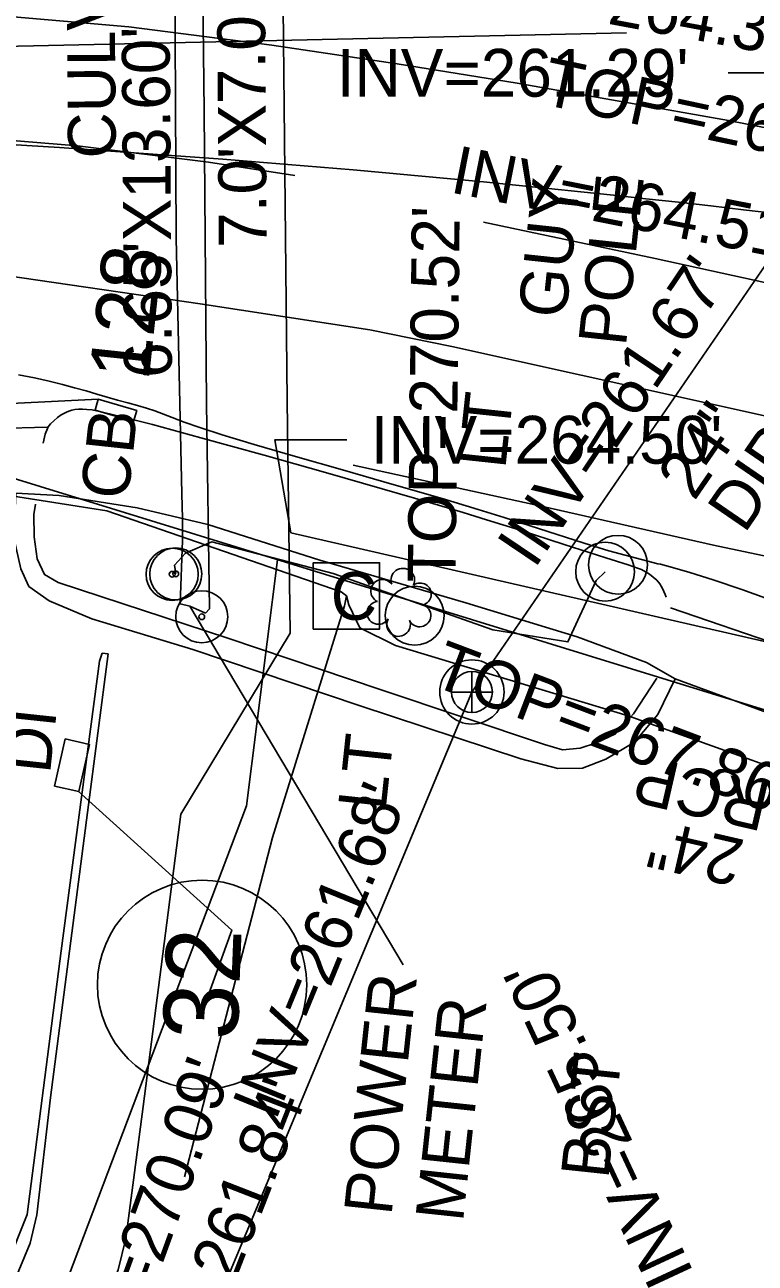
# Model space of a CAD drawing. Extents: x 2100323 to 2109811, y 740376 to 749755.
# Drawn here: x 2105500.5 to 2105561.5, y 742054.8 to 742158.5 of the extents above; entities that cross this region are included whole.
import ezdxf

# ---------------------------------------------------------------- set-up
doc = ezdxf.new("R2010")
doc.units = 0
for name, color, linetype in [('COGO Default Point Number', 7, 'Continuous'), ('Exist Horizontal Alignment', 7, 'Continuous'), ('Exist Other Culture Located Object CELL', 7, 'Continuous'), ('Exist Other Culture Sign CELL', 7, 'Continuous'), ('Exist Property Owner Number CELL', 7, 'Continuous'), ('Exist Right of Way Easement Line', 7, 'Continuous'), ('Exist Right of Way Line', 7, 'Continuous'), ('Exist Roads Curbs', 7, 'Continuous'), ('Exist Roads EOP', 7, 'Continuous'), ('Exist Roads EOP Other', 7, 'Continuous'), ('Exist Roads EOP Text', 7, 'Continuous'), ('Exist Roads EOT', 7, 'Continuous'), ('Exist Structure Major Box Culvert or Tunnel Topo', 7, 'Continuous'), ('Exist Structure Major Box Culvert or Tunnel Topo Text', 7, 'Continuous'), ('Exist Structure Minor Catch Basin', 7, 'Continuous'), ('Exist Structure Minor Catch Basin Text', 7, 'Continuous'), ('Exist Structure Minor Catch Basin Top Elevation', 7, 'Continuous'), ('Exist Structure Minor Drop Inlet', 7, 'Continuous'), ('Exist Structure Minor Drop Inlet Text', 7, 'Continuous'), ('Exist Structure Minor Drop Inlet Top Elevation', 7, 'Continuous'), ('Exist Structure Minor Pipes RCP 18 Inch Invert', 7, 'Continuous'), ('Exist Structure Minor Pipes RCP 24 Inch', 7, 'Continuous'), ('Exist Structure Minor Pipes RCP 24 Inch Invert', 7, 'Continuous'), ('Exist Structure Minor Pipes RCP 24 Inch Leader', 7, 'Continuous'), ('Exist Structure Minor Pipes RCP 24 Inch Text', 7, 'Continuous'), ('Exist Structure Minor Pipes RCP 60 Inch Invert', 7, 'Continuous'), ('Exist Structure Minor Storm Sewer Manhole Text', 7, 'Continuous'), ('Exist Utilities Other Located Object CELL', 7, 'Continuous'), ('Exist Utilities Other Located Object Text', 7, 'Continuous'), ('Exist Utilities Other Pole CELL', 7, 'Continuous'), ('Exist Utilities Other Pole Text', 7, 'Continuous'), ('Exist Utilities Power UG Cable SUE LOS B', 7, 'Continuous'), ('Exist Utilities Sanitary Sewer Manhole CELL', 7, 'Continuous'), ('Exist Utilities Sanitary Sewer Manhole Text', 7, 'Continuous'), ('Exist Utilities Sanitary Sewer UG Line', 7, 'Continuous'), ('Exist Utilities Sanitary Sewer UG Line Invert Elevation', 7, 'Continuous'), ('Exist Utilities Sanitary Sewer UG Line Text', 7, 'Continuous'), ('Exist Utilities TV Pedestal CELL', 7, 'Continuous'), ('Exist Utilities TV UG Cable SUE LOS B', 7, 'Continuous'), ('Exist Utilities Water UG Line SUE LOS B', 7, 'Continuous'), ('Exist Vegetation Shrub CELL', 7, 'Continuous')]:
    doc.layers.add(name, color=color, linetype=linetype)

msp = doc.modelspace()

# ---------------------------------------------------------------- linework, layer by layer
at = {"layer": 'Exist Horizontal Alignment'}
msp.add_arc((2105432.5, 741050.49), 1100, 71.91861, 90.1558, dxfattribs=at)
at = {"layer": 'Exist Other Culture Located Object CELL'}
for radius in [2.18, 0.24]:
    msp.add_circle((2105512.8, 742112.5), radius, dxfattribs=at)
at = {"layer": 'Exist Other Culture Sign CELL'}
for radius in [2.18, 0.24]:
    msp.add_circle((2105515.27, 742108.95), radius, dxfattribs=at)
at = {"layer": 'Exist Property Owner Number CELL'}
msp.add_circle((2105515.3, 742078.15), 8.75, dxfattribs=at)
at = {"layer": 'Exist Right of Way Easement Line'}
msp.add_lwpolyline([(2105410.16, 741805.17), (2105519.01, 742093.13), (2105521.61, 742113.72)], dxfattribs=at)
at = {"layer": 'Exist Right of Way Line'}
msp.add_line((2105563.87, 742100.68), (2105498.4, 742120.88), dxfattribs=at)
at = {"layer": 'Exist Roads Curbs'}
for points in [[(2105502.01, 742123.48), (2105502.19, 742124.22), (2105502.36, 742124.7), (2105502.43, 742124.85), (2105502.63, 742125.08), (2105502.89, 742125.35), (2105503.22, 742125.63), (2105503.52, 742125.84), (2105503.79, 742125.99), (2105504.02, 742126.1), (2105504.23, 742126.18), (2105504.42, 742126.24), (2105504.66, 742126.29), (2105504.96, 742126.31), (2105505.31, 742126.32), (2105505.67, 742126.3), (2105506.12, 742126.25), (2105507.07, 742126.05), (2105508.6, 742125.69), (2105511.16, 742125.03), (2105515.2, 742123.93), (2105520.49, 742122.46), (2105525.62, 742121.02), (2105530.35, 742119.66), (2105534.32, 742118.51), (2105537.13, 742117.67), (2105539.08, 742117.07), (2105541.8, 742116.21), (2105545.57, 742115), (2105549.06, 742113.88), (2105550.94, 742113.28), (2105551.41, 742113.13), (2105551.71, 742113.02), (2105552.03, 742112.89), (2105552.37, 742112.72), (2105552.7, 742112.52), (2105553.03, 742112.27), (2105553.32, 742112), (2105553.57, 742111.69), (2105553.8, 742111.31), (2105554.02, 742110.82), (2105554.1, 742110.59)], [(2105553.32, 742103.8), (2105551.36, 742100.82), (2105549.87, 742099.16), (2105548.29, 742098.4), (2105546.91, 742097.95), (2105545.43, 742097.82), (2105543.93, 742098.25), (2105530.18, 742102.87), (2105517.46, 742107.16), (2105503.27, 742111.8), (2105502.13, 742112.48), (2105501.5, 742113.79), (2105501.25, 742115.63), (2105501.23, 742117.5), (2105501.36, 742118.36)]]:
    msp.add_lwpolyline(points, dxfattribs=at)
at = {"layer": 'Exist Roads EOP'}
msp.add_lwpolyline([(2105563.45, 742110.15), (2105560.43, 742111.24), (2105558.02, 742112.05), (2105556.09, 742112.66), (2105554.63, 742113.08), (2105553.62, 742113.34), (2105553.42, 742113.37), (2105549.32, 742114.45), (2105547.26, 742115.1), (2105543.44, 742116.32), (2105540.56, 742117.24), (2105538.37, 742117.93), (2105535.38, 742118.83), (2105531.36, 742119.99), (2105527.03, 742121.24), (2105523.11, 742122.37), (2105519.66, 742123.37), (2105516.98, 742124.18), (2105515.11, 742124.78), (2105513.8, 742125.23), (2105512.8, 742125.61), (2105512.06, 742125.91), (2105511.35, 742126.18), (2105510.64, 742126.4), (2105509.89, 742126.62), (2105509.08, 742126.84), (2105508.23, 742127.07), (2105507.36, 742127.32), (2105506.5, 742127.57), (2105505.6, 742127.84), (2105504.64, 742128.11), (2105503.62, 742128.38), (2105502.5, 742128.65), (2105501.28, 742128.94), (2105499.94, 742129.19)], dxfattribs=at)
at = {"layer": 'Exist Roads EOP Other'}
for p, q in [((2105482.06, 742124.25), (2105502.35, 742124.82)), ((2105554.47, 742109.68), (2105573.81, 742103.1))]:
    msp.add_line(p, q, dxfattribs=at)
for points in [[(2105537.34, 742110.12), (2105525.14, 742113.68), (2105515.77, 742116.67), (2105509.87, 742118.05), (2105503.36, 742119.09), (2105499.72, 742119.28), (2105499.55, 742115.55), (2105500.13, 742112.96), (2105500.82, 742111.49), (2105502.5, 742110.27), (2105506.07, 742108.78), (2105514.52, 742106.22), (2105528.52, 742101.49), (2105541.94, 742097.06), (2105545.05, 742096.25), (2105547.12, 742096.27), (2105549.07, 742097.03), (2105551.46, 742098.45), (2105553.41, 742100.77), (2105554.87, 742103.76), (2105552.46, 742105.11), (2105546.67, 742107.26), (2105537.34, 742110.12)], [(2105570.07, 742098.21), (2105562.22, 742101.04), (2105554.87, 742103.76)]]:
    msp.add_lwpolyline(points, dxfattribs=at)
at = {"layer": 'Exist Roads EOT'}
for points in [[(2105657.81, 742129.81), (2105634.16, 742135.14), (2105611.86, 742139.96), (2105588.07, 742144.82), (2105559.32, 742150.47), (2105541.65, 742153.6), (2105531.62, 742155.21), (2105521.13, 742156.77), (2105509.17, 742158.31), (2105495.65, 742159.49), (2105488.07, 742159.96), (2105478.84, 742160.35), (2105462.89, 742160.91), (2105447.16, 742161.3), (2105427.37, 742161.57), (2105409.26, 742161.54), (2105395.33, 742161.48), (2105374.36, 742161.43), (2105358.31, 742161.43), (2105338.52, 742161.51)], [(2105247.07, 742149.99), (2105256.27, 742150.18), (2105268.69, 742150.23), (2105288.69, 742150.41), (2105310.21, 742150.6), (2105330.16, 742150.78), (2105350.7, 742150.88), (2105364.69, 742150.79), (2105386.5, 742150.93), (2105404.87, 742150.98), (2105431.15, 742150.93), (2105450.53, 742150.9), (2105467.45, 742150.65), (2105484.77, 742149.99), (2105504.89, 742148.35), (2105515.83, 742146.99), (2105523.05, 742145.86)], [(2105538.83, 742141.97), (2105553.17, 742138.93), (2105568.85, 742135.51), (2105583.12, 742132.44), (2105598.56, 742129.03), (2105611.07, 742126.35), (2105632.04, 742121.86), (2105646.94, 742118.71), (2105654.68, 742117.08)], [(2105655.74, 742104.8), (2105646.38, 742106.9), (2105616.35, 742113.65), (2105607.95, 742115.51), (2105575.77, 742122.82), (2105568.62, 742124.37), (2105536.18, 742131.56), (2105529.32, 742132.97), (2105515.15, 742135.14), (2105497.51, 742137.7), (2105492.22, 742138.12), (2105487.99, 742138.32), (2105457.15, 742138.93), (2105451.39, 742139.04), (2105416.99, 742139.14), (2105376.88, 742139.55), (2105336.5, 742139.93), (2105295.5, 742140.03), (2105255.89, 742139.52), (2105246.58, 742139.28)], [(2105527.93, 742121.64), (2105543.79, 742118.18), (2105558.06, 742114.95), (2105572.62, 742111.86), (2105587.35, 742108.5), (2105601.06, 742105.45), (2105616.18, 742102.07), (2105630.52, 742098.9), (2105644.91, 742095.69), (2105659.34, 742092.43), (2105673.67, 742089.31), (2105688.56, 742086.03), (2105702.56, 742082.88), (2105716.65, 742079.8), (2105731.9, 742076.4), (2105745.41, 742073.34), (2105760.09, 742070.06), (2105774.47, 742066.87), (2105789.4, 742063.55), (2105803.96, 742060.38)]]:
    msp.add_lwpolyline(points, dxfattribs=at)
at = {"layer": 'Exist Structure Major Box Culvert or Tunnel Topo'}
for p, q in [((2105513.67, 742115.34), (2105513.47, 742110.03)), ((2105515.58, 742109.25), (2105515.91, 742109.6)), ((2105505.72, 742092.56), (2105507.45, 742105.85)), ((2105506.71, 742105.24), (2105506.94, 742105.91)), ((2105507.45, 742105.85), (2105506.94, 742105.91))]:
    msp.add_line(p, q, dxfattribs=at)
for points in [[(2105521.73, 742188.71), (2105521.98, 742171.05), (2105522.17, 742151.65), (2105522.41, 742127.02), (2105522.67, 742107.56), (2105513.52, 742092.43), (2105510.37, 742067.95), (2105508.91, 742056.91), (2105508.29, 742054.3), (2105498.41, 742030.53), (2105486.89, 742002.84), (2105476.67, 741978.66)], [(2105512.89, 742188.85), (2105513, 742168.9), (2105513.14, 742140.64), (2105513.6, 742119.24), (2105513.67, 742117.17), (2105513.67, 742115.34)], [(2105514.99, 742188.8), (2105515.25, 742170.7), (2105515.46, 742151.25), (2105515.66, 742126.78), (2105515.91, 742109.6)], [(2105515.58, 742109.25), (2105514.28, 742109.83), (2105513.47, 742110.03)], [(2105506.71, 742105.24), (2105503.52, 742080.98), (2105500.67, 742058.92), (2105490.17, 742032.61)], [(2105505.72, 742092.56), (2105502.63, 742068.72), (2105501.47, 742058.89), (2105500.92, 742056.53), (2105491.61, 742034.12), (2105479.7, 742005.71), (2105469.74, 741981.84)]]:
    msp.add_lwpolyline(points, dxfattribs=at)
at = {"layer": 'Exist Structure Minor Catch Basin'}
msp.add_lwpolyline([(2105506.62, 742127.16), (2105506.35, 742126.24), (2105509.57, 742125.29), (2105509.84, 742126.2)], close=True, dxfattribs=at)
at = {"layer": 'Exist Structure Minor Catch Basin Top Elevation'}
msp.add_lwpolyline([(2105506.62, 742127.16), (2105495.97, 742126.63), (2105489.98, 742126.89)], dxfattribs=at)
at = {"layer": 'Exist Structure Minor Drop Inlet'}
msp.add_lwpolyline([(2105503.86, 742098.73), (2105502.96, 742094.77), (2105504.98, 742094.31), (2105505.88, 742098.27)], close=True, dxfattribs=at)
at = {"layer": 'Exist Structure Minor Drop Inlet Top Elevation'}
msp.add_lwpolyline([(2105504.95, 742094.36), (2105517.79, 742082.72), (2105515.74, 742077.08)], dxfattribs=at)
at = {"layer": 'Exist Structure Minor Pipes RCP 24 Inch'}
msp.add_line((2105522.71, 742115.98), (2105577.65, 742103.34), dxfattribs=at)
at = {"layer": 'Exist Structure Minor Pipes RCP 24 Inch Leader'}
msp.add_lwpolyline([(2105522.71, 742115.98), (2105521.39, 742123.76), (2105527.39, 742123.76)], dxfattribs=at)
at = {"layer": 'Exist Utilities Other Located Object CELL'}
for radius in [2.18, 0.24]:
    msp.add_circle((2105513.1, 742112.53), radius, dxfattribs=at)
at = {"layer": 'Exist Utilities Other Located Object Text'}
msp.add_line((2105514.28, 742109.83), (2105532.11, 742079.82), dxfattribs=at)
at = {"layer": 'Exist Utilities Other Pole CELL'}
for centre in [(2105549, 742112.72), (2105550.08, 742113.3), (2105533.08, 742109.04)]:
    msp.add_circle(centre, 2.46, dxfattribs=at)
at = {"layer": 'Exist Utilities Power UG Cable SUE LOS B'}
msp.add_line((2105513.11, 742112.58), (2105512.98, 742113.26), dxfattribs=at)
for points in [[(2105539.61, 742107.86), (2105526.27, 742112.58), (2105516.12, 742115.22), (2105513.92, 742114.26), (2105512.98, 742113.26)], [(2105549, 742112.72), (2105548.25, 742111.97), (2105545.89, 742106.84), (2105539.61, 742107.86)]]:
    msp.add_lwpolyline(points, dxfattribs=at)
at = {"layer": 'Exist Utilities Sanitary Sewer Manhole CELL'}
msp.add_lwpolyline([(2105537.86, 742104.36), (2105537.86, 742100.93), (2105537.86, 742102.65), (2105539.58, 742102.65), (2105536.15, 742102.65)], dxfattribs=at)
for radius in [2.69, 1.71]:
    msp.add_circle((2105537.86, 742102.65), radius, dxfattribs=at)
at = {"layer": 'Exist Utilities Sanitary Sewer UG Line'}
for p, q in [((2105579.37, 742163.1), (2105537.86, 742102.65)), ((2105537.86, 742102.65), (2105392.84, 741754.89))]:
    msp.add_line(p, q, dxfattribs=at)
at = {"layer": 'Exist Utilities Sanitary Sewer UG Line Invert Elevation'}
msp.add_lwpolyline([(2105576.35, 742160.37), (2105565.3, 742154.47), (2105559.3, 742154.47)], dxfattribs=at)
at = {"layer": 'Exist Utilities TV Pedestal CELL'}
msp.add_line((2105527.37, 742110.69), (2105527.37, 742110.69), dxfattribs=at)
msp.add_lwpolyline([(2105524.59, 742107.92), (2105530.14, 742107.92), (2105530.14, 742113.47), (2105524.59, 742113.47), (2105524.59, 742107.92)], dxfattribs=at)
at = {"layer": 'Exist Utilities TV UG Cable SUE LOS B'}
for p, q in [((2105507.34, 742117.8), (2105526.92, 742111.03)), ((2105526.92, 742111.03), (2105527.37, 742110.69)), ((2105527.37, 742110.69), (2105527.2, 742109.87)), ((2105527.57, 742109.95), (2105527.37, 742110.69))]:
    msp.add_line(p, q, dxfattribs=at)
for points in [[(2105400.2, 742119.49), (2105408.11, 742122.3), (2105430.5, 742122.51), (2105448.6, 742123.23), (2105465.08, 742123.15), (2105486.05, 742121.17), (2105507.34, 742117.8)], [(2105527.2, 742109.87), (2105521.18, 742090.48), (2105513.83, 742062.07)], [(2105527.57, 742109.95), (2105528.48, 742108.03), (2105531.48, 742106.55), (2105550.94, 742100.66), (2105578.9, 742090.61), (2105608.91, 742080.59), (2105614.57, 742077.87), (2105615.9, 742075.61), (2105615.54, 742071.58), (2105612.36, 742057.27), (2105605.05, 742034.49), (2105599.03, 742015.51), (2105593.63, 741996.28)]]:
    msp.add_lwpolyline(points, dxfattribs=at)
at = {"layer": 'Exist Utilities Water UG Line SUE LOS B'}
msp.add_lwpolyline([(2105141.76, 742148.57), (2105173.54, 742149.74), (2105248.39, 742151.12), (2105374.06, 742154.97), (2105475.73, 742156.18), (2105550.78, 742157.81)], dxfattribs=at)
at = {"layer": 'Exist Vegetation Shrub CELL'}
msp.add_line((2105531.86, 742109.97), (2105531.86, 742109.97), dxfattribs=at)
for centre, radius, start, end in [((2105532.08, 742112.01), 0.99, 334.8391, 200.4717), ((2105530.37, 742111.1), 0.968, 35.8908, 245.4216), ((2105533.53, 742110.84), 0.929, 284.4567, 126.0861), ((2105530.05, 742109.27), 0.955, 95.1099, 327.9534), ((2105533.49, 742109.04), 0.937, 204.9913, 73.4601), ((2105531.73, 742108.29), 0.984, 151.2797, 21.387)]:
    msp.add_arc(centre, radius, start, end, dxfattribs=at)

# ---------------------------------------------------------------- texts
at = {"layer": 'COGO Default Point Number'}
msp.add_text('128', height=5, rotation=83.8864, dxfattribs=at).set_placement((2105510.83, 742128.61))
at = {"layer": 'Exist Property Owner Number CELL'}
msp.add_text('32', height=6.25, rotation=87.7944, dxfattribs=at).set_placement((2105518.25, 742073.46))
at = {"layer": 'Exist Roads EOP Text'}
msp.add_text('BST', height=4, rotation=83.8864, dxfattribs=at).set_placement((2105549.27, 742061.84))
at = {"layer": 'Exist Structure Major Box Culvert or Tunnel Topo Text'}
for s, p in [('CULVERT#5', (2105508.09, 742147.31)), ("7.0'X7.0' RCBC", (2105520.7, 742139.84)), ("6.65'X13.60' RCBC", (2105512.78, 742128.95))]:
    msp.add_text(s, height=4, rotation=90.3929, dxfattribs=at).set_placement(p)
at = {"layer": 'Exist Structure Minor Catch Basin Text'}
msp.add_text('CB', height=4, rotation=83.8864, dxfattribs=at).set_placement((2105509.11, 742118.66))
at = {"layer": 'Exist Structure Minor Catch Basin Top Elevation'}
msp.add_text("TOP=267.86'", height=4, rotation=339.2468, dxfattribs=at).set_placement((2105534.31, 742103.28))
at = {"layer": 'Exist Structure Minor Drop Inlet Text'}
msp.add_text('DI', height=4, rotation=83.8864, dxfattribs=at).set_placement((2105502.58, 742095.74))
at = {"layer": 'Exist Structure Minor Drop Inlet Top Elevation'}
msp.add_text("TOP=270.09'", height=4, rotation=70.0187, dxfattribs=at).set_placement((2105507.14, 742041.43))
at = {"layer": 'Exist Structure Minor Pipes RCP 18 Inch Invert'}
for s, rotation, p in [("INV=264.33'", 349.432, (2105537.29, 742160.8)), ("INV=264.51'", 348.7412, (2105535.93, 742144.48))]:
    msp.add_text(s, height=4, rotation=rotation, dxfattribs=at).set_placement(p)
at = {"layer": 'Exist Structure Minor Pipes RCP 24 Inch Invert'}
msp.add_text("INV=264.50'", height=4, dxfattribs=at).set_placement((2105529.39, 742121.76))
at = {"layer": 'Exist Structure Minor Pipes RCP 24 Inch Text'}
for s, p in [('RCP', (2105563.01, 742094.86)), ('24"', (2105560.81, 742090.23))]:
    msp.add_text(s, height=4, rotation=167.0443, dxfattribs=at).set_placement(p)
at = {"layer": 'Exist Structure Minor Pipes RCP 60 Inch Invert'}
msp.add_text("INV=261.84'", height=4, rotation=68.7258, dxfattribs=at).set_placement((2105513.62, 742041.87))
at = {"layer": 'Exist Structure Minor Storm Sewer Manhole Text'}
msp.add_text("TOP=269.38'", height=4, rotation=347.8999, dxfattribs=at).set_placement((2105543.54, 742151.88))
at = {"layer": 'Exist Utilities Other Located Object Text'}
for s, p in [('POWER', (2105531.13, 742058.77)), ('METER', (2105537.11, 742058.23))]:
    msp.add_text(s, height=4, rotation=83.8864, dxfattribs=at).set_placement(p)
at = {"layer": 'Exist Utilities Other Pole Text'}
for s, p in [('GUY', (2105545.7, 742133.83)), ('POLE', (2105550.73, 742131.51)), ('LT', (2105540.65, 742121.26)), ('LT', (2105530.64, 742092.66))]:
    msp.add_text(s, height=4, rotation=83.8864, dxfattribs=at).set_placement(p)
at = {"layer": 'Exist Utilities Sanitary Sewer Manhole Text'}
msp.add_text("TOP=270.52'", height=4, rotation=89.3342, dxfattribs=at).set_placement((2105536.48, 742111.8))
at = {"layer": 'Exist Utilities Sanitary Sewer UG Line Invert Elevation'}
msp.add_text("INV=261.29'", height=4, dxfattribs=at).set_placement((2105526.56, 742152.47))
for s, rotation, p in [("INV=261.67'", 56.0081, (2105543.09, 742112.88)), ("INV=261.68'", 67.7301, (2105521.44, 742066.68)), ("INV=265.50'", 114.9749, (2105556.45, 742054.02))]:
    msp.add_text(s, height=4, rotation=rotation, dxfattribs=at).set_placement(p)
at = {"layer": 'Exist Utilities Sanitary Sewer UG Line Text'}
for s, p in [('24"', (2105556.45, 742118.56)), ('DIP', (2105560.65, 742115.83))]:
    msp.add_text(s, height=4, rotation=55.5254, dxfattribs=at).set_placement(p)
at = {"layer": 'Exist Utilities TV Pedestal CELL'}
msp.add_text('C', height=4, dxfattribs=at).set_placement((2105526.06, 742108.69))

doc.saveas('drawing.dxf')
